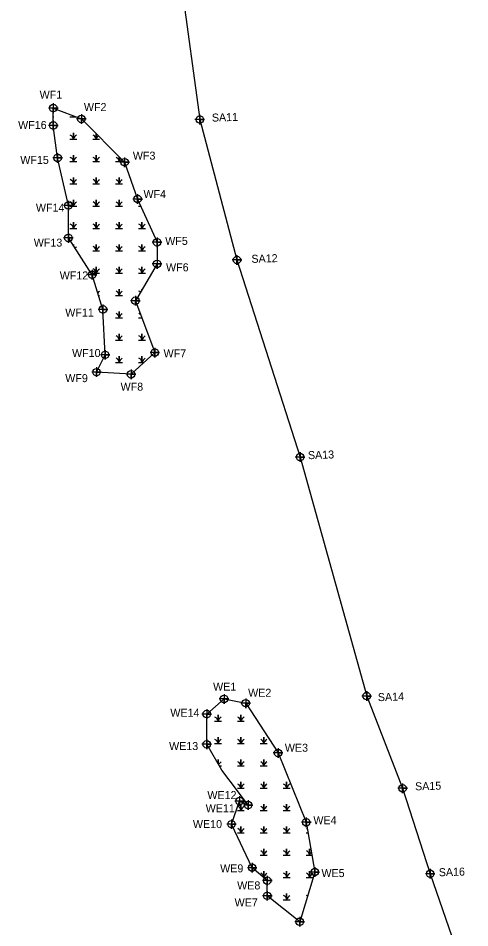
# Model space of a CAD drawing. Extents: x 1616941 to 1621864, y 896903 to 900301.
# Drawn here: x 1619590 to 1619873, y 898775 to 899343 of the extents above; entities that cross this region are included whole.
import ezdxf

# ---------------------------------------------------------------- set-up
doc = ezdxf.new("R2010")
doc.units = 0
for name, color, linetype in [('Exist Hydro Swamp or Marsh', 7, 'Continuous'), ('Sheet Block Revision CELL', 7, 'Continuous'), ('Sheet Layout Plan Border', 7, 'Continuous'), ('Sheet North Arrow Point CELL', 7, 'Continuous'), ('Sheet Plan CELL', 7, 'Continuous'), ('Sheet Plot Border Outside CELL', 7, 'Continuous'), ('Sheet Sticker Exception Certification CELL', 7, 'Continuous')]:
    doc.layers.add(name, color=color, linetype=linetype)

msp = doc.modelspace()

# ---------------------------------------------------------------- linework, layer by layer
at = {"layer": 'Exist Hydro Swamp or Marsh'}
for p, q in [((1619612.28, 899281.16), (1619612.7, 899281.16)), ((1619665.6, 899225.38), (1619667.02, 899225.38)), ((1619626.94, 899197.49), (1619627, 899197.49)), ((1619640.66, 899169.6), (1619641.3, 899169.6)), ((1619665.6, 899155.65), (1619667.66, 899155.65)), ((1619716.13, 898875.68), (1619717.47, 898875.68)), ((1619756.08, 898875.68), (1619756.17, 898875.68)), ((1619770.38, 898833.85), (1619771.62, 898833.85)), ((1619770.38, 898792.01), (1619770.59, 898792.01))]:
    msp.add_line(p, q, dxfattribs=at)
for points in [[(1619622.7, 899281.16), (1619624.85, 899281.16), (1619624.85, 899281.8)], [(1619624.85, 899281.8), (1619624.85, 899281.16), (1619626.52, 899281.16)], [(1619622.7, 899267.21), (1619624.85, 899267.21), (1619624.85, 899271.16), (1619624.85, 899267.21), (1619627, 899267.21)], [(1619637, 899267.21), (1619639.15, 899267.21), (1619639.15, 899270.59)], [(1619639.15, 899270.59), (1619639.15, 899267.21), (1619641.3, 899267.21)], [(1619622.7, 899253.27), (1619624.85, 899253.27), (1619624.85, 899257.21), (1619624.85, 899253.27), (1619627, 899253.27)], [(1619637, 899253.27), (1619639.15, 899253.27), (1619639.15, 899257.21), (1619639.15, 899253.27), (1619641.3, 899253.27)], [(1619651.3, 899253.27), (1619653.45, 899253.27), (1619653.45, 899256.29)], [(1619653.45, 899256.29), (1619653.45, 899253.27), (1619655.6, 899253.27)], [(1619622.7, 899239.32), (1619624.85, 899239.32), (1619624.85, 899243.27), (1619624.85, 899239.32), (1619627, 899239.32)], [(1619637, 899239.32), (1619639.15, 899239.32), (1619639.15, 899243.27), (1619639.15, 899239.32), (1619641.3, 899239.32)], [(1619651.3, 899239.32), (1619653.45, 899239.32), (1619653.45, 899243.27), (1619653.45, 899239.32), (1619655.6, 899239.32)], [(1619622.7, 899225.38), (1619624.85, 899225.38), (1619624.85, 899229.32), (1619624.85, 899225.38), (1619627, 899225.38)], [(1619637, 899225.38), (1619639.15, 899225.38), (1619639.15, 899229.32), (1619639.15, 899225.38), (1619641.3, 899225.38)], [(1619651.3, 899225.38), (1619653.45, 899225.38), (1619653.45, 899229.32), (1619653.45, 899225.38), (1619655.6, 899225.38)], [(1619622.7, 899211.43), (1619624.85, 899211.43), (1619624.85, 899215.38), (1619624.85, 899211.43), (1619627, 899211.43)], [(1619637, 899211.43), (1619639.15, 899211.43), (1619639.15, 899215.38), (1619639.15, 899211.43), (1619641.3, 899211.43)], [(1619651.3, 899211.43), (1619653.45, 899211.43), (1619653.45, 899215.38), (1619653.45, 899211.43), (1619655.6, 899211.43)], [(1619665.6, 899211.43), (1619667.75, 899211.43), (1619667.75, 899215.38), (1619667.75, 899211.43), (1619669.9, 899211.43)], [(1619624.85, 899200.72), (1619624.85, 899201.43), (1619624.85, 899200.72)], [(1619637, 899197.49), (1619639.15, 899197.49), (1619639.15, 899201.43), (1619639.15, 899197.49), (1619641.3, 899197.49)], [(1619651.3, 899197.49), (1619653.45, 899197.49), (1619653.45, 899201.43), (1619653.45, 899197.49), (1619655.6, 899197.49)], [(1619665.6, 899197.49), (1619667.75, 899197.49), (1619667.75, 899201.43), (1619667.75, 899197.49), (1619669.9, 899197.49)], [(1619637, 899183.54), (1619639.15, 899183.54), (1619639.15, 899187.49), (1619639.15, 899183.54), (1619641.3, 899183.54)], [(1619651.3, 899183.54), (1619653.45, 899183.54), (1619653.45, 899187.49), (1619653.45, 899183.54), (1619655.6, 899183.54)], [(1619665.6, 899183.54), (1619667.75, 899183.54), (1619667.75, 899187.49), (1619667.75, 899183.54), (1619669.9, 899183.54)], [(1619651.3, 899169.6), (1619653.45, 899169.6), (1619653.45, 899173.54), (1619653.45, 899169.6), (1619655.6, 899169.6)], [(1619667.75, 899173.26), (1619667.75, 899173.54), (1619667.75, 899173.26)], [(1619651.3, 899155.65), (1619653.45, 899155.65), (1619653.45, 899159.6), (1619653.45, 899155.65), (1619655.6, 899155.65)], [(1619651.3, 899141.71), (1619653.45, 899141.71), (1619653.45, 899145.65), (1619653.45, 899141.71), (1619655.6, 899141.71)], [(1619665.6, 899141.71), (1619667.75, 899141.71), (1619667.75, 899145.65), (1619667.75, 899141.71), (1619669.9, 899141.71)], [(1619651.3, 899127.76), (1619653.45, 899127.76), (1619653.45, 899131.71), (1619653.45, 899127.76), (1619655.6, 899127.76)], [(1619665.6, 899127.76), (1619667.75, 899127.76), (1619667.75, 899131.71), (1619667.75, 899127.76), (1619669.12, 899127.76)], [(1619713.17, 898903.57), (1619715.32, 898903.57), (1619715.32, 898907.52), (1619715.32, 898903.57), (1619717.47, 898903.57)], [(1619727.47, 898903.57), (1619729.62, 898903.57), (1619729.62, 898907.52), (1619729.62, 898903.57), (1619731.77, 898903.57)], [(1619713.17, 898889.63), (1619715.32, 898889.63), (1619715.32, 898893.57), (1619715.32, 898889.63), (1619717.47, 898889.63)], [(1619727.47, 898889.63), (1619729.62, 898889.63), (1619729.62, 898893.57), (1619729.62, 898889.63), (1619731.77, 898889.63)], [(1619741.77, 898889.63), (1619743.93, 898889.63), (1619743.93, 898893.57), (1619743.93, 898889.63), (1619746.08, 898889.63)], [(1619715.32, 898877.06), (1619715.32, 898879.63), (1619715.32, 898877.06)], [(1619727.47, 898875.68), (1619729.62, 898875.68), (1619729.62, 898879.63), (1619729.62, 898875.68), (1619731.77, 898875.68)], [(1619741.77, 898875.68), (1619743.93, 898875.68), (1619743.93, 898879.63), (1619743.93, 898875.68), (1619746.08, 898875.68)], [(1619727.47, 898861.74), (1619729.62, 898861.74), (1619729.62, 898865.68), (1619729.62, 898861.74), (1619731.77, 898861.74)], [(1619741.77, 898861.74), (1619743.93, 898861.74), (1619743.93, 898865.68), (1619743.93, 898861.74), (1619746.08, 898861.74)], [(1619756.08, 898861.74), (1619758.23, 898861.74), (1619758.23, 898865.68), (1619758.23, 898861.74), (1619760.38, 898861.74)], [(1619727.47, 898847.79), (1619729.62, 898847.79), (1619729.62, 898851.74), (1619729.62, 898847.79), (1619731.77, 898847.79)], [(1619741.77, 898847.79), (1619743.93, 898847.79), (1619743.93, 898851.74), (1619743.93, 898847.79), (1619746.08, 898847.79)], [(1619756.08, 898847.79), (1619758.23, 898847.79), (1619758.23, 898851.74), (1619758.23, 898847.79), (1619760.38, 898847.79)], [(1619727.47, 898833.85), (1619729.62, 898833.85), (1619729.62, 898837.79), (1619729.62, 898833.85), (1619731.77, 898833.85)], [(1619741.77, 898833.85), (1619743.93, 898833.85), (1619743.93, 898837.79), (1619743.93, 898833.85), (1619746.08, 898833.85)], [(1619756.08, 898833.85), (1619758.23, 898833.85), (1619758.23, 898837.79), (1619758.23, 898833.85), (1619760.38, 898833.85)], [(1619741.77, 898819.9), (1619743.93, 898819.9), (1619743.93, 898823.85), (1619743.93, 898819.9), (1619746.08, 898819.9)], [(1619756.08, 898819.9), (1619758.23, 898819.9), (1619758.23, 898823.85), (1619758.23, 898819.9), (1619760.38, 898819.9)], [(1619770.38, 898819.9), (1619772.53, 898819.9), (1619772.53, 898823.85), (1619772.53, 898819.9), (1619774.05, 898819.9)], [(1619743.81, 898805.96), (1619743.93, 898805.96), (1619743.93, 898809.9), (1619743.93, 898805.96), (1619746.08, 898805.96)], [(1619756.08, 898805.96), (1619758.23, 898805.96), (1619758.23, 898809.9), (1619758.23, 898805.96), (1619760.38, 898805.96)], [(1619770.38, 898805.96), (1619772.53, 898805.96), (1619772.53, 898809.9), (1619772.53, 898805.96), (1619774.68, 898805.96)], [(1619756.08, 898792.01), (1619758.23, 898792.01), (1619758.23, 898795.96), (1619758.23, 898792.01), (1619760.38, 898792.01)]]:
    msp.add_lwpolyline(points, dxfattribs=at)
for centre, radius, start, end in [((1619615.11, 899279.64), 4.81, 122.1274, 125.9795), ((1619621.78, 899280.94), 3.07, 4.1403, 17.3497), ((1619629.41, 899279.64), 4.81, 154.4485, 161.6222), ((1619621.78, 899266.99), 3.07, 4.1403, 67.535), ((1619629.41, 899265.7), 4.81, 122.1274, 161.6222), ((1619636.08, 899266.99), 3.07, 4.1403, 67.535), ((1619643.71, 899265.7), 4.81, 132.2356, 161.6222), ((1619621.78, 899253.05), 3.07, 4.1403, 67.535), ((1619629.41, 899251.75), 4.81, 122.1274, 161.6222), ((1619636.08, 899253.05), 3.07, 4.1403, 67.535), ((1619643.71, 899251.75), 4.81, 122.1274, 161.6222), ((1619650.38, 899253.05), 3.07, 4.1403, 67.535), ((1619658.01, 899251.75), 4.81, 135.2351, 161.6222), ((1619621.78, 899239.1), 3.07, 4.1403, 67.535), ((1619629.41, 899237.81), 4.81, 122.1274, 161.6222), ((1619636.08, 899239.1), 3.07, 4.1403, 67.535), ((1619643.71, 899237.81), 4.81, 122.1274, 161.6222), ((1619650.38, 899239.1), 3.07, 4.1403, 67.535), ((1619658.01, 899237.81), 4.81, 122.1274, 161.6222), ((1619621.78, 899225.16), 3.07, 4.1403, 67.535), ((1619629.41, 899223.86), 4.81, 122.1274, 161.6222), ((1619636.08, 899225.16), 3.07, 4.1403, 67.535), ((1619643.71, 899223.86), 4.81, 122.1274, 161.6222), ((1619650.38, 899225.16), 3.07, 4.1403, 67.535), ((1619658.01, 899223.86), 4.81, 122.1274, 161.6222), ((1619621.78, 899211.21), 3.07, 4.1403, 67.535), ((1619629.41, 899209.92), 4.81, 122.1274, 161.6222), ((1619636.08, 899211.21), 3.07, 4.1403, 67.535), ((1619643.71, 899209.92), 4.81, 122.1274, 161.6222), ((1619650.38, 899211.21), 3.07, 4.1403, 67.535), ((1619658.01, 899209.92), 4.81, 122.1274, 161.6222), ((1619664.68, 899211.21), 3.07, 4.1403, 67.535), ((1619672.31, 899209.92), 4.81, 122.1274, 161.6222), ((1619629.41, 899195.97), 4.81, 122.1274, 137.9552), ((1619636.08, 899197.27), 3.07, 4.1403, 67.535), ((1619643.71, 899195.97), 4.81, 122.1274, 161.6222), ((1619650.38, 899197.27), 3.07, 4.1403, 67.535), ((1619658.01, 899195.97), 4.81, 122.1274, 161.6222), ((1619664.68, 899197.27), 3.07, 4.1403, 67.535), ((1619672.31, 899195.97), 4.81, 122.1274, 161.6222), ((1619636.08, 899183.32), 3.07, 4.1403, 67.535), ((1619643.71, 899182.03), 4.81, 122.1274, 161.6222), ((1619650.38, 899183.32), 3.07, 4.1403, 67.535), ((1619658.01, 899182.03), 4.81, 122.1274, 161.6222), ((1619664.68, 899183.32), 3.07, 4.1403, 67.535), ((1619672.31, 899182.03), 4.81, 122.1274, 161.6222), ((1619643.71, 899168.08), 4.81, 122.1274, 138.0986), ((1619650.38, 899169.38), 3.07, 4.1403, 67.535), ((1619658.01, 899168.08), 4.81, 122.1274, 161.6222), ((1619664.68, 899169.38), 3.07, 46.8495, 67.535), ((1619650.38, 899155.43), 3.07, 4.1403, 67.535), ((1619658.01, 899154.14), 4.81, 122.1274, 161.6222), ((1619664.68, 899155.43), 3.07, 42.0475, 67.535), ((1619650.38, 899141.49), 3.07, 4.1403, 67.535), ((1619658.01, 899140.19), 4.81, 122.1274, 161.6222), ((1619664.68, 899141.49), 3.07, 4.1403, 67.535), ((1619672.31, 899140.19), 4.81, 122.1274, 161.6222), ((1619650.38, 899127.54), 3.07, 4.1403, 67.535), ((1619658.01, 899126.25), 4.81, 122.1274, 161.6222), ((1619664.68, 899127.54), 3.07, 4.1403, 67.535), ((1619672.31, 899126.25), 4.81, 122.1274, 161.6222), ((1619712.26, 898903.35), 3.07, 4.1403, 67.535), ((1619719.88, 898902.06), 4.81, 122.1274, 161.6222), ((1619726.56, 898903.35), 3.07, 4.1403, 67.535), ((1619734.18, 898902.06), 4.81, 122.1274, 161.6222), ((1619712.26, 898889.4), 3.07, 4.1403, 67.535), ((1619719.88, 898888.11), 4.81, 122.1274, 161.6222), ((1619726.56, 898889.4), 3.07, 4.1403, 67.535), ((1619734.18, 898888.11), 4.81, 122.1274, 161.6222), ((1619740.86, 898889.4), 3.07, 4.1403, 67.535), ((1619748.49, 898888.11), 4.81, 122.1274, 161.6222), ((1619719.88, 898874.17), 4.81, 122.1274, 151.3212), ((1619726.56, 898875.46), 3.07, 4.1403, 67.535), ((1619734.18, 898874.17), 4.81, 122.1274, 161.6222), ((1619740.86, 898875.46), 3.07, 4.1403, 67.535), ((1619748.49, 898874.17), 4.81, 122.1274, 161.6222), ((1619726.56, 898861.51), 3.07, 4.1403, 67.535), ((1619734.18, 898860.22), 4.81, 122.1274, 161.6222), ((1619740.86, 898861.51), 3.07, 4.1403, 67.535), ((1619748.49, 898860.22), 4.81, 122.1274, 161.6222), ((1619755.16, 898861.51), 3.07, 4.1403, 67.535), ((1619762.79, 898860.22), 4.81, 122.1274, 161.6222), ((1619726.56, 898847.57), 3.07, 4.1403, 67.535), ((1619734.18, 898846.28), 4.81, 122.1274, 161.6222), ((1619740.86, 898847.57), 3.07, 4.1403, 67.535), ((1619748.49, 898846.28), 4.81, 122.1274, 161.6222), ((1619755.16, 898847.57), 3.07, 4.1403, 67.535), ((1619762.79, 898846.28), 4.81, 122.1274, 161.6222), ((1619726.56, 898833.62), 3.07, 4.1403, 67.535), ((1619734.18, 898832.33), 4.81, 122.1274, 161.6222), ((1619740.86, 898833.62), 3.07, 4.1403, 67.535), ((1619748.49, 898832.33), 4.81, 122.1274, 161.6222), ((1619755.16, 898833.62), 3.07, 4.1403, 67.535), ((1619762.79, 898832.33), 4.81, 122.1274, 161.6222), ((1619769.46, 898833.62), 3.07, 55.0323, 67.535), ((1619740.86, 898819.68), 3.07, 4.1403, 67.535), ((1619748.49, 898818.39), 4.81, 122.1274, 161.6222), ((1619755.16, 898819.68), 3.07, 4.1403, 67.535), ((1619762.79, 898818.39), 4.81, 122.1274, 161.6222), ((1619769.46, 898819.68), 3.07, 4.1403, 67.535), ((1619777.09, 898818.39), 4.81, 134.5642, 161.6222), ((1619740.86, 898805.73), 3.07, 4.1403, 67.535), ((1619748.49, 898804.44), 4.81, 122.1274, 161.6222), ((1619755.16, 898805.73), 3.07, 4.1403, 67.535), ((1619762.79, 898804.44), 4.81, 122.1274, 161.6222), ((1619769.46, 898805.73), 3.07, 4.1403, 67.535), ((1619777.09, 898804.44), 4.81, 122.1274, 161.6222), ((1619755.16, 898791.79), 3.07, 4.1403, 67.535), ((1619762.79, 898790.49), 4.81, 122.1274, 161.6222), ((1619769.46, 898791.79), 3.07, 53.7051, 67.535)]:
    msp.add_arc(centre, radius, start, end, dxfattribs=at)
at = {"layer": 'Sheet Block Revision CELL'}
for points in [[(1619612.28, 899286.64), (1619629.86, 899279.88), (1619656.9, 899252.84), (1619665.01, 899229.85), (1619677.18, 899202.81), (1619677.18, 899189.29), (1619663.66, 899166.31), (1619675.83, 899133.86), (1619660.96, 899120.34), (1619639.32, 899121.69), (1619644.73, 899132.51), (1619643.38, 899160.9), (1619636.62, 899182.53), (1619621.75, 899205.51), (1619621.75, 899225.79), (1619614.99, 899255.54), (1619612.28, 899275.82)], [(1619732.61, 898914.83), (1619752.89, 898883.73), (1619770.47, 898840.47), (1619775.88, 898809.37), (1619766.41, 898778.28), (1619746.13, 898794.5), (1619746.13, 898803.96), (1619736.67, 898812.08), (1619723.76, 898839.27), (1619728.83, 898853.72), (1619734.18, 898851.2), (1619727.51, 898860.01), (1619717.74, 898872.92), (1619708.28, 898889.14), (1619708.28, 898908.07), (1619719.09, 898917.53)]]:
    msp.add_lwpolyline(points, close=True, dxfattribs=at)
at = {"layer": 'Sheet North Arrow Point CELL'}
for points in [[(1619703.92, 899282.5), (1619703.92, 899276.5), (1619703.92, 899279.5), (1619706.92, 899279.5), (1619700.92, 899279.5)], [(1619727.18, 899194.75), (1619727.18, 899188.75), (1619727.18, 899191.75), (1619730.18, 899191.75), (1619724.18, 899191.75)], [(1619766.66, 899071.6), (1619766.66, 899065.6), (1619766.66, 899068.6), (1619769.66, 899068.6), (1619763.66, 899068.6)], [(1619808.28, 898922.27), (1619808.28, 898916.27), (1619808.28, 898919.27), (1619811.28, 898919.27), (1619805.28, 898919.27)], [(1619830.77, 898864.65), (1619830.77, 898858.65), (1619830.77, 898861.65), (1619833.77, 898861.65), (1619827.77, 898861.65)], [(1619848, 898811.3), (1619848, 898805.3), (1619848, 898808.3), (1619851, 898808.3), (1619845, 898808.3)]]:
    msp.add_lwpolyline(points, dxfattribs=at)
for centre in [(1619703.92, 899279.5), (1619727.18, 899191.75), (1619766.66, 899068.6), (1619808.28, 898919.27), (1619830.77, 898861.65), (1619848, 898808.3)]:
    msp.add_circle(centre, 2.34, dxfattribs=at)
at = {"layer": 'Sheet Plan CELL'}
for points in [[(1619612.28, 899289.64), (1619612.28, 899283.64), (1619612.28, 899286.64), (1619615.28, 899286.64), (1619609.28, 899286.64)], [(1619629.86, 899282.88), (1619629.86, 899276.88), (1619629.86, 899279.88), (1619632.86, 899279.88), (1619626.86, 899279.88)], [(1619612.28, 899278.82), (1619612.28, 899272.82), (1619612.28, 899275.82), (1619615.28, 899275.82), (1619609.28, 899275.82)], [(1619614.99, 899258.54), (1619614.99, 899252.54), (1619614.99, 899255.54), (1619617.99, 899255.54), (1619611.99, 899255.54)], [(1619656.9, 899255.84), (1619656.9, 899249.84), (1619656.9, 899252.84), (1619659.9, 899252.84), (1619653.9, 899252.84)], [(1619665.01, 899232.85), (1619665.01, 899226.85), (1619665.01, 899229.85), (1619668.01, 899229.85), (1619662.01, 899229.85)], [(1619621.75, 899228.79), (1619621.75, 899222.79), (1619621.75, 899225.79), (1619624.75, 899225.79), (1619618.75, 899225.79)], [(1619621.75, 899208.51), (1619621.75, 899202.51), (1619621.75, 899205.51), (1619624.75, 899205.51), (1619618.75, 899205.51)], [(1619677.18, 899205.81), (1619677.18, 899199.81), (1619677.18, 899202.81), (1619680.18, 899202.81), (1619674.18, 899202.81)], [(1619677.18, 899192.29), (1619677.18, 899186.29), (1619677.18, 899189.29), (1619680.18, 899189.29), (1619674.18, 899189.29)], [(1619636.62, 899185.53), (1619636.62, 899179.53), (1619636.62, 899182.53), (1619639.62, 899182.53), (1619633.62, 899182.53)], [(1619663.66, 899169.31), (1619663.66, 899163.31), (1619663.66, 899166.31), (1619666.66, 899166.31), (1619660.66, 899166.31)], [(1619643.38, 899163.9), (1619643.38, 899157.9), (1619643.38, 899160.9), (1619646.38, 899160.9), (1619640.38, 899160.9)], [(1619644.73, 899135.51), (1619644.73, 899129.51), (1619644.73, 899132.51), (1619647.73, 899132.51), (1619641.73, 899132.51)], [(1619675.83, 899136.86), (1619675.83, 899130.86), (1619675.83, 899133.86), (1619678.83, 899133.86), (1619672.83, 899133.86)], [(1619639.32, 899124.69), (1619639.32, 899118.69), (1619639.32, 899121.69), (1619642.32, 899121.69), (1619636.32, 899121.69)], [(1619660.96, 899123.34), (1619660.96, 899117.34), (1619660.96, 899120.34), (1619663.96, 899120.34), (1619657.96, 899120.34)], [(1619719.09, 898920.53), (1619719.09, 898914.53), (1619719.09, 898917.53), (1619722.09, 898917.53), (1619716.09, 898917.53)], [(1619732.61, 898917.83), (1619732.61, 898911.83), (1619732.61, 898914.83), (1619735.61, 898914.83), (1619729.61, 898914.83)], [(1619708.28, 898911.07), (1619708.28, 898905.07), (1619708.28, 898908.07), (1619711.28, 898908.07), (1619705.28, 898908.07)], [(1619708.28, 898892.14), (1619708.28, 898886.14), (1619708.28, 898889.14), (1619711.28, 898889.14), (1619705.28, 898889.14)], [(1619752.89, 898886.73), (1619752.89, 898880.73), (1619752.89, 898883.73), (1619755.89, 898883.73), (1619749.89, 898883.73)], [(1619728.83, 898856.72), (1619728.83, 898850.72), (1619728.83, 898853.72), (1619731.83, 898853.72), (1619725.83, 898853.72)], [(1619734.18, 898854.2), (1619734.18, 898848.2), (1619734.18, 898851.2), (1619737.18, 898851.2), (1619731.18, 898851.2)], [(1619770.47, 898843.47), (1619770.47, 898837.47), (1619770.47, 898840.47), (1619773.47, 898840.47), (1619767.47, 898840.47)], [(1619723.76, 898842.27), (1619723.76, 898836.27), (1619723.76, 898839.27), (1619726.76, 898839.27), (1619720.76, 898839.27)], [(1619736.67, 898815.08), (1619736.67, 898809.08), (1619736.67, 898812.08), (1619739.67, 898812.08), (1619733.67, 898812.08)], [(1619775.88, 898812.37), (1619775.88, 898806.37), (1619775.88, 898809.37), (1619778.88, 898809.37), (1619772.88, 898809.37)], [(1619746.13, 898806.96), (1619746.13, 898800.96), (1619746.13, 898803.96), (1619749.13, 898803.96), (1619743.13, 898803.96)], [(1619746.13, 898797.5), (1619746.13, 898791.5), (1619746.13, 898794.5), (1619749.13, 898794.5), (1619743.13, 898794.5)], [(1619766.41, 898781.28), (1619766.41, 898775.28), (1619766.41, 898778.28), (1619769.41, 898778.28), (1619763.41, 898778.28)]]:
    msp.add_lwpolyline(points, dxfattribs=at)
for centre in [(1619612.28, 899286.64), (1619629.86, 899279.88), (1619612.28, 899275.82), (1619614.99, 899255.54), (1619656.9, 899252.84), (1619665.01, 899229.85), (1619621.75, 899225.79), (1619621.75, 899205.51), (1619677.18, 899202.81), (1619677.18, 899189.29), (1619636.62, 899182.53), (1619663.66, 899166.31), (1619643.38, 899160.9), (1619644.73, 899132.51), (1619675.83, 899133.86), (1619639.32, 899121.69), (1619660.96, 899120.34), (1619719.09, 898917.53), (1619732.61, 898914.83), (1619708.28, 898908.07), (1619708.28, 898889.14), (1619752.89, 898883.73), (1619728.83, 898853.72), (1619734.18, 898851.2), (1619723.76, 898839.27), (1619770.47, 898840.47), (1619736.67, 898812.08), (1619775.88, 898809.37), (1619746.13, 898803.96), (1619746.13, 898794.5), (1619766.41, 898778.28)]:
    msp.add_circle(centre, 2.34, dxfattribs=at)
at = {"layer": 'Sheet Sticker Exception Certification CELL'}
msp.add_lwpolyline([(1619621.98, 900133.22), (1619625.99, 900061.52), (1619632.34, 899960.76), (1619647.76, 899895.1), (1619647.51, 899820.39), (1619654.04, 899725.51), (1619663.09, 899629.38), (1619675.68, 899525.53), (1619687.04, 899464.22), (1619692.39, 899363.46), (1619703.92, 899279.5), (1619727.18, 899191.75), (1619766.66, 899068.6), (1619808.28, 898919.27), (1619830.77, 898861.65), (1619848, 898808.3), (1619911.6, 898624.59), (1619941.08, 898421.92)], dxfattribs=at)

# ---------------------------------------------------------------- texts
at = {"layer": 'Sheet Layout Plan Border'}
for s, p in [('SA11', (1619711.55, 899278.17)), ('SA12', (1619736.31, 899189.94)), ('SA13', (1619771.62, 899067.28)), ('SA14', (1619815.34, 898916.09)), ('SA15', (1619838.62, 898860.36)), ('SA16', (1619853.44, 898806.67))]:
    msp.add_text(s, height=5, rotation=1.7576, dxfattribs=at).set_placement(p)
at = {"layer": 'Sheet Plot Border Outside CELL'}
for s, p in [('WF1', (1619603.77, 899292.54)), ('WF2', (1619631.45, 899284.81)), ('WF16', (1619590.32, 899273.62)), ('WF3', (1619662.06, 899254.45)), ('WF15', (1619591.66, 899251.78)), ('WF4', (1619668.71, 899230.48)), ('WF14', (1619601.43, 899221.95)), ('WF13', (1619600.1, 899200.11)), ('WF5', (1619682.29, 899201.19)), ('WF12', (1619616.33, 899179.6)), ('WF6', (1619682.82, 899184.68)), ('WF11', (1619619.79, 899156.43)), ('WF10', (1619624.05, 899131.13)), ('WF7', (1619681.27, 899130.87)), ('WF9', (1619619.79, 899115.42)), ('WF8', (1619654.39, 899110.1)), ('WE1', (1619712.25, 898922.65)), ('WE2', (1619734.15, 898918.84)), ('WE14', (1619685.51, 898906.34)), ('WE13', (1619684.72, 898885.57)), ('WE3', (1619757.11, 898884.51)), ('WE12', (1619708.67, 898854.95)), ('WE11', (1619707.61, 898846.69)), ('WE4', (1619774.94, 898839.23)), ('WE10', (1619699.62, 898836.84)), ('WE9', (1619716.66, 898809.14)), ('WE5', (1619780, 898806.21)), ('WE8', (1619727.3, 898798.49)), ('WE7', (1619725.7, 898787.84))]:
    msp.add_text(s, height=5, dxfattribs=at).set_placement(p)

doc.saveas('drawing.dxf')
